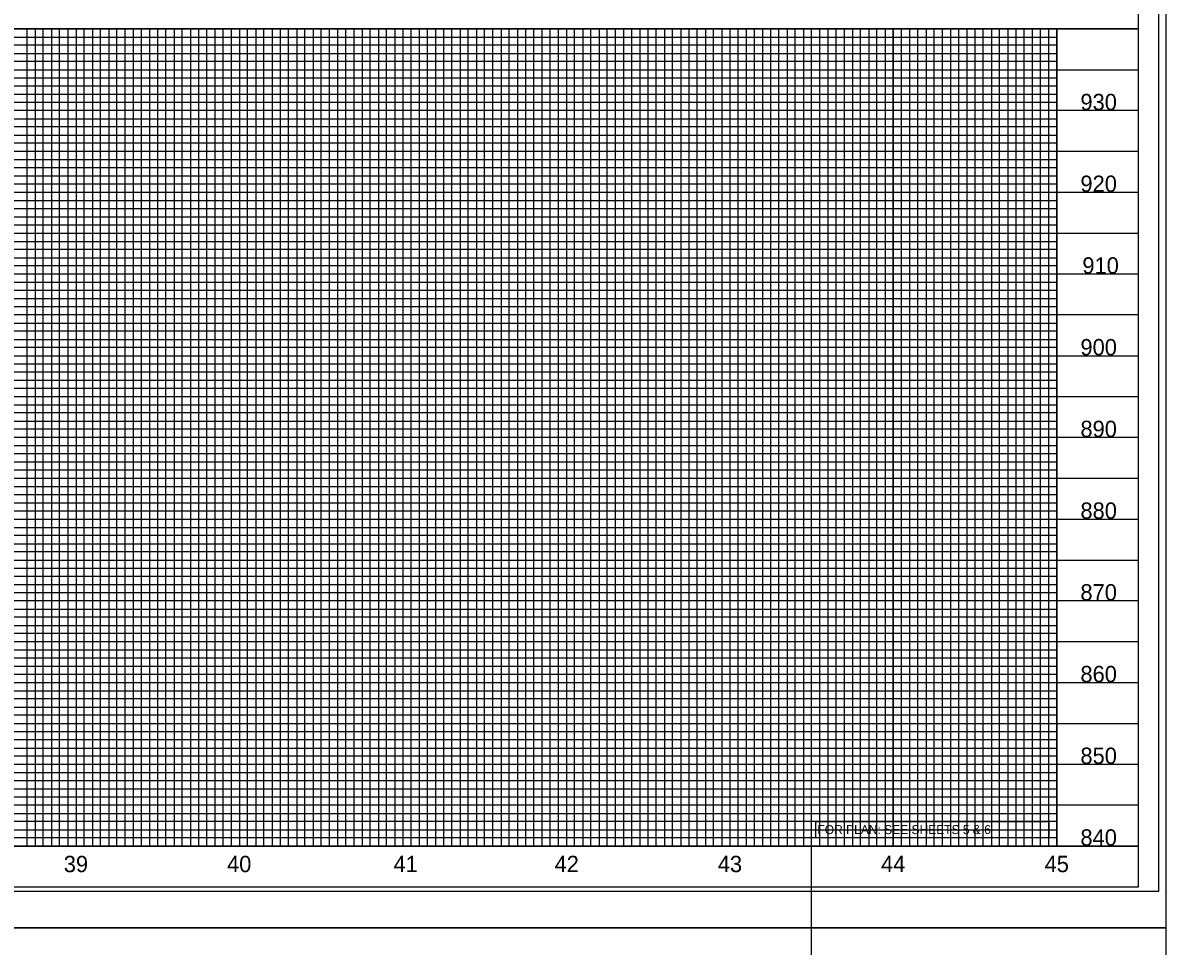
# Model space of a CAD drawing. Extents: x 1967929 to 1975641, y 546296 to 568534.
# Drawn here: x 1970849 to 1971549, y 567423 to 567988 of the extents above; entities that cross this region are included whole.
import ezdxf

# ---------------------------------------------------------------- set-up
doc = ezdxf.new("R2010")
doc.units = 0
for name, color, linetype in [('Exist Vertical Profile Horizontal Axis Label Major', 7, 'Continuous'), ('Exist Vertical Profile Vertical Axis Label', 7, 'Continuous'), ('Old_Level_60', 7, 'Continuous'), ('Prop Grid Mask', 7, 'Continuous'), ('Scratch_Level_3', 7, 'Continuous'), ('Sheet Cutting Line CELL', 7, 'Continuous'), ('Sheet Plot Border Inside CELL', 7, 'Continuous'), ('Sheet Plot Border Outside CELL', 7, 'Continuous'), ('Sheet Profile CELL', 7, 'Continuous'), ('Sheet Profile Grid Major CELL', 7, 'Continuous'), ('Sheet Profile Grid Middle CELL', 7, 'Continuous'), ('Sheet Profile Grid Minor CELL', 7, 'Continuous')]:
    doc.layers.add(name, color=color, linetype=linetype)

msp = doc.modelspace()

# ---------------------------------------------------------------- linework, layer by layer
at = {"layer": 'Old_Level_60'}
msp.add_line((1971548.95, 567456.36), (1971548.95, 567456.36), dxfattribs=at)
at = {"layer": 'Prop Grid Mask'}
msp.add_lwpolyline([(1971334.04, 567498.93), (1971476.5, 567498.93), (1971476.5, 567488.91), (1971334.04, 567488.91)], close=True, dxfattribs=at)
at = {"layer": 'Scratch_Level_3'}
for points in [[(1970081.45, 567983.86), (1970081.45, 567483.86), (1971481.45, 567483.86), (1971481.45, 567983.86)], [(1970081.45, 567983.86), (1970081.45, 567483.86), (1971381.45, 567483.86), (1971381.45, 567983.86)], [(1970081.45, 567983.86), (1970081.45, 567483.86), (1971481.45, 567483.86), (1971481.45, 567983.86)], [(1970081.45, 567983.86), (1970081.45, 567483.86), (1971481.45, 567483.86), (1971481.45, 567752.23), (1971481.45, 567983.86), (1971331.4, 567983.86)], [(1970081.45, 567508.86), (1970081.45, 567008.86), (1971481.45, 567008.86), (1971481.5, 567312.53), (1971331.45, 567312.51), (1971331.4, 567508.86)]]:
    msp.add_lwpolyline(points, close=True, dxfattribs=at)
at = {"layer": 'Sheet Cutting Line CELL'}
msp.add_line((1969864.45, 567433.86), (1971548.45, 567433.86), dxfattribs=at)
at = {"layer": 'Sheet Plot Border Inside CELL'}
msp.add_lwpolyline([(1969877.45, 567456.31), (1971543.95, 567456.31), (1971543.95, 568511.41), (1969877.45, 568511.41)], close=True, dxfattribs=at)
at = {"layer": 'Sheet Plot Border Outside CELL'}
for points in [[(1969864.45, 567433.86), (1971548.45, 567433.86), (1971548.45, 568533.86), (1969864.45, 568533.86)], [(1969864.45, 566333.86), (1971548.45, 566333.86), (1971548.45, 567433.86), (1969864.45, 567433.86)]]:
    msp.add_lwpolyline(points, close=True, dxfattribs=at)
at = {"layer": 'Sheet Profile CELL'}
for p, q in [((1971531.45, 567983.86), (1970031.45, 567983.86)), ((1971531.45, 567483.86), (1970031.45, 567483.86))]:
    msp.add_line(p, q, dxfattribs=at)
msp.add_lwpolyline([(1971531.45, 568508.86), (1970031.45, 568508.86), (1970031.45, 567458.86), (1971531.45, 567458.86)], close=True, dxfattribs=at)
at = {"layer": 'Sheet Profile Grid Major CELL'}
for points in [[(1971531.45, 567933.86), (1970031.45, 567933.86), (1970031.45, 567983.86), (1971531.45, 567983.86)], [(1970881.45, 567983.86), (1970881.45, 567483.86), (1970931.45, 567483.86), (1970931.45, 567983.86)], [(1970981.45, 567983.86), (1970981.45, 567483.86), (1971031.45, 567483.86), (1971031.45, 567983.86)], [(1971081.45, 567983.86), (1971081.45, 567483.86), (1971131.45, 567483.86), (1971131.45, 567983.86)], [(1971181.45, 567983.86), (1971181.45, 567483.86), (1971231.45, 567483.86), (1971231.45, 567983.86)], [(1971281.45, 567983.86), (1971281.45, 567483.86), (1971331.45, 567483.86), (1971331.45, 567983.86)], [(1971381.45, 567983.86), (1971381.45, 567483.86), (1971431.45, 567483.86), (1971431.45, 567983.86)], [(1971481.45, 567983.86), (1971481.45, 567483.86), (1971531.45, 567483.86)], [(1971531.45, 567833.86), (1970031.45, 567833.86), (1970031.45, 567883.86), (1971531.45, 567883.86)], [(1971531.45, 567733.86), (1970031.45, 567733.86), (1970031.45, 567783.86), (1971531.45, 567783.86)], [(1971531.45, 567633.86), (1970031.45, 567633.86), (1970031.45, 567683.86), (1971531.45, 567683.86)], [(1971531.45, 567533.86), (1970031.45, 567533.86), (1970031.45, 567583.86), (1971531.45, 567583.86)]]:
    msp.add_lwpolyline(points, dxfattribs=at)
at = {"layer": 'Sheet Profile Grid Middle CELL'}
for points in [[(1970031.45, 567983.86), (1970031.45, 567958.86), (1971531.45, 567958.86)], [(1970856.45, 567983.86), (1970856.45, 567483.86), (1970906.45, 567483.86), (1970906.45, 567983.86)], [(1970956.45, 567983.86), (1970956.45, 567483.86), (1971006.45, 567483.86), (1971006.45, 567983.86)], [(1971056.45, 567983.86), (1971056.45, 567483.86), (1971106.45, 567483.86), (1971106.45, 567983.86)], [(1971156.45, 567983.86), (1971156.45, 567483.86), (1971206.45, 567483.86), (1971206.45, 567983.86)], [(1971256.45, 567983.86), (1971256.45, 567483.86), (1971306.45, 567483.86), (1971306.45, 567983.86)], [(1971356.45, 567983.86), (1971356.45, 567483.86), (1971406.45, 567483.86), (1971406.45, 567983.86)], [(1971456.45, 567983.86), (1971456.45, 567483.86)], [(1971531.45, 567908.86), (1970031.45, 567908.86), (1970031.45, 567858.86), (1971531.45, 567858.86)], [(1971531.45, 567808.86), (1970031.45, 567808.86), (1970031.45, 567758.86), (1971531.45, 567758.86)], [(1971531.45, 567708.86), (1970031.45, 567708.86), (1970031.45, 567658.86), (1971531.45, 567658.86)], [(1971531.45, 567608.86), (1970031.45, 567608.86), (1970031.45, 567558.86), (1971531.45, 567558.86)], [(1971531.45, 567508.86), (1970031.45, 567508.86)]]:
    msp.add_lwpolyline(points, dxfattribs=at)
at = {"layer": 'Sheet Profile Grid Minor CELL'}
for points in [[(1970851.45, 567983.86), (1970851.45, 567483.86), (1970861.45, 567483.86), (1970861.45, 567983.86)], [(1970866.45, 567983.86), (1970866.45, 567483.86), (1970871.45, 567483.86), (1970871.45, 567983.86)], [(1970876.45, 567983.86), (1970876.45, 567483.86), (1970886.45, 567483.86), (1970886.45, 567983.86)], [(1970891.45, 567983.86), (1970891.45, 567483.86), (1970896.45, 567483.86), (1970896.45, 567983.86)], [(1970901.45, 567983.86), (1970901.45, 567483.86), (1970911.45, 567483.86), (1970911.45, 567983.86)], [(1970916.45, 567983.86), (1970916.45, 567483.86), (1970921.45, 567483.86), (1970921.45, 567983.86)], [(1970926.45, 567983.86), (1970926.45, 567483.86), (1970936.45, 567483.86), (1970936.45, 567983.86)], [(1970941.45, 567983.86), (1970941.45, 567483.86), (1970946.45, 567483.86), (1970946.45, 567983.86)], [(1970951.45, 567983.86), (1970951.45, 567483.86), (1970961.45, 567483.86), (1970961.45, 567983.86)], [(1970966.45, 567983.86), (1970966.45, 567483.86), (1970971.45, 567483.86), (1970971.45, 567983.86)], [(1970976.45, 567983.86), (1970976.45, 567483.86), (1970986.45, 567483.86), (1970986.45, 567983.86)], [(1970991.45, 567983.86), (1970991.45, 567483.86), (1970996.45, 567483.86), (1970996.45, 567983.86)], [(1971001.45, 567983.86), (1971001.45, 567483.86), (1971011.45, 567483.86), (1971011.45, 567983.86)], [(1971016.45, 567983.86), (1971016.45, 567483.86), (1971021.45, 567483.86), (1971021.45, 567983.86)], [(1971026.45, 567983.86), (1971026.45, 567483.86), (1971036.45, 567483.86), (1971036.45, 567983.86)], [(1971041.45, 567983.86), (1971041.45, 567483.86), (1971046.45, 567483.86), (1971046.45, 567983.86)], [(1971051.45, 567983.86), (1971051.45, 567483.86), (1971061.45, 567483.86), (1971061.45, 567983.86)], [(1971066.45, 567983.86), (1971066.45, 567483.86), (1971071.45, 567483.86), (1971071.45, 567983.86)], [(1971076.45, 567983.86), (1971076.45, 567483.86), (1971086.45, 567483.86), (1971086.45, 567983.86)], [(1971091.45, 567983.86), (1971091.45, 567483.86), (1971096.45, 567483.86), (1971096.45, 567983.86)], [(1971101.45, 567983.86), (1971101.45, 567483.86)], [(1971101.45, 567483.86), (1971111.45, 567483.86), (1971111.45, 567983.86)], [(1971116.45, 567983.86), (1971116.45, 567483.86), (1971121.45, 567483.86), (1971121.45, 567983.86)], [(1971126.45, 567983.86), (1971126.45, 567483.86), (1971136.45, 567483.86), (1971136.45, 567983.86)], [(1971141.45, 567983.86), (1971141.45, 567483.86), (1971146.45, 567483.86), (1971146.45, 567983.86)], [(1971151.45, 567983.86), (1971151.45, 567483.86), (1971161.45, 567483.86), (1971161.45, 567983.86)], [(1971166.45, 567983.86), (1971166.45, 567483.86), (1971171.45, 567483.86), (1971171.45, 567983.86)], [(1971176.45, 567983.86), (1971176.45, 567483.86), (1971186.45, 567483.86), (1971186.45, 567983.86)], [(1971191.45, 567983.86), (1971191.45, 567483.86), (1971196.45, 567483.86), (1971196.45, 567983.86)], [(1971201.45, 567983.86), (1971201.45, 567483.86), (1971211.45, 567483.86), (1971211.45, 567983.86)], [(1971216.45, 567983.86), (1971216.45, 567483.86), (1971221.45, 567483.86), (1971221.45, 567983.86)], [(1971226.45, 567983.86), (1971226.45, 567483.86), (1971236.45, 567483.86), (1971236.45, 567983.86)], [(1971241.45, 567983.86), (1971241.45, 567483.86), (1971246.45, 567483.86), (1971246.45, 567983.86)], [(1971251.45, 567983.86), (1971251.45, 567483.86), (1971261.45, 567483.86), (1971261.45, 567983.86)], [(1971266.45, 567983.86), (1971266.45, 567483.86), (1971271.45, 567483.86), (1971271.45, 567983.86)], [(1971276.45, 567983.86), (1971276.45, 567483.86), (1971286.45, 567483.86), (1971286.45, 567983.86)], [(1971291.45, 567983.86), (1971291.45, 567483.86), (1971296.45, 567483.86), (1971296.45, 567983.86)], [(1971301.45, 567983.86), (1971301.45, 567483.86), (1971311.45, 567483.86), (1971311.45, 567983.86)], [(1971316.45, 567983.86), (1971316.45, 567483.86), (1971321.45, 567483.86), (1971321.45, 567983.86)], [(1971326.45, 567983.86), (1971326.45, 567483.86), (1971336.45, 567483.86), (1971336.45, 567983.86)], [(1971341.45, 567983.86), (1971341.45, 567483.86), (1971346.45, 567483.86), (1971346.45, 567983.86)], [(1971351.45, 567983.86), (1971351.45, 567483.86), (1971361.45, 567483.86), (1971361.45, 567983.86)], [(1971366.45, 567983.86), (1971366.45, 567483.86), (1971371.45, 567483.86), (1971371.45, 567983.86)], [(1971376.45, 567983.86), (1971376.45, 567483.86), (1971386.45, 567483.86), (1971386.45, 567983.86)], [(1971391.45, 567983.86), (1971391.45, 567483.86), (1971396.45, 567483.86), (1971396.45, 567983.86)], [(1971401.45, 567983.86), (1971401.45, 567483.86), (1971411.45, 567483.86), (1971411.45, 567983.86)], [(1971416.45, 567983.86), (1971416.45, 567483.86)], [(1971416.45, 567483.86), (1971421.45, 567483.86), (1971421.45, 567983.86)], [(1971426.45, 567983.86), (1971426.45, 567483.86), (1971436.45, 567483.86), (1971436.45, 567983.86)], [(1971441.45, 567983.86), (1971441.45, 567483.86), (1971446.45, 567483.86), (1971446.45, 567983.86)], [(1971451.45, 567983.86), (1971451.45, 567483.86), (1971461.45, 567483.86), (1971461.45, 567983.86)], [(1971466.45, 567983.86), (1971466.45, 567483.86), (1971471.45, 567483.86), (1971471.45, 567983.86)], [(1971476.45, 567983.86), (1971476.45, 567483.86), (1971486.45, 567483.86)], [(1970081.45, 567978.86), (1971481.45, 567978.86)], [(1971481.45, 567973.86), (1970081.45, 567973.86), (1970081.45, 567968.86), (1971481.45, 567968.86)], [(1971481.45, 567963.86), (1970081.45, 567963.86), (1970081.45, 567953.86), (1971481.45, 567953.86)], [(1971481.45, 567948.86), (1970081.45, 567948.86), (1970081.45, 567943.86), (1971481.45, 567943.86)], [(1971481.45, 567938.86), (1970081.45, 567938.86), (1970081.45, 567928.86), (1971481.45, 567928.86)], [(1971481.45, 567923.86), (1970081.45, 567923.86), (1970081.45, 567918.86), (1971481.45, 567918.86)], [(1971481.45, 567913.86), (1970081.45, 567913.86), (1970081.45, 567903.86), (1971481.45, 567903.86)], [(1971481.45, 567898.86), (1970081.45, 567898.86), (1970081.45, 567893.86), (1971481.45, 567893.86)], [(1971481.45, 567888.86), (1970081.45, 567888.86), (1970081.45, 567878.86), (1971481.45, 567878.86)], [(1971481.45, 567873.86), (1970081.45, 567873.86), (1970081.45, 567868.86), (1971481.45, 567868.86)], [(1971481.45, 567863.86), (1970081.45, 567863.86), (1970081.45, 567853.86), (1971481.45, 567853.86)], [(1971481.45, 567848.86), (1970081.45, 567848.86), (1970081.45, 567843.86), (1971481.45, 567843.86)], [(1971481.45, 567838.86), (1970081.45, 567838.86), (1970081.45, 567828.86), (1971481.45, 567828.86)], [(1971481.45, 567823.86), (1970081.45, 567823.86), (1970081.45, 567818.86), (1971481.45, 567818.86)], [(1971481.45, 567813.86), (1970081.45, 567813.86), (1970081.45, 567803.86), (1971481.45, 567803.86)], [(1971481.45, 567798.86), (1970081.45, 567798.86), (1970081.45, 567793.86), (1971481.45, 567793.86)], [(1971481.45, 567788.86), (1970081.45, 567788.86), (1970081.45, 567778.86), (1971481.45, 567778.86)], [(1971481.45, 567773.86), (1970081.45, 567773.86), (1970081.45, 567768.86), (1971481.45, 567768.86)], [(1971481.45, 567763.86), (1970081.45, 567763.86), (1970081.45, 567753.86), (1971481.45, 567753.86)], [(1971481.45, 567748.86), (1970081.45, 567748.86), (1970081.45, 567743.86), (1971481.45, 567743.86)], [(1971481.45, 567738.86), (1970081.45, 567738.86), (1970081.45, 567728.86), (1971481.45, 567728.86)], [(1971481.45, 567723.86), (1970081.45, 567723.86), (1970081.45, 567718.86), (1971481.45, 567718.86)], [(1971481.45, 567713.86), (1970081.45, 567713.86), (1970081.45, 567703.86), (1971481.45, 567703.86)], [(1971481.45, 567698.86), (1970081.45, 567698.86), (1970081.45, 567693.86), (1971481.45, 567693.86)], [(1971481.45, 567688.86), (1970081.45, 567688.86)], [(1970081.45, 567678.86), (1971481.45, 567678.86)], [(1971481.45, 567673.86), (1970081.45, 567673.86), (1970081.45, 567668.86), (1971481.45, 567668.86)], [(1971481.45, 567663.86), (1970081.45, 567663.86)], [(1970081.45, 567653.86), (1971481.45, 567653.86)], [(1971481.45, 567648.86), (1970081.45, 567648.86), (1970081.45, 567643.86), (1971481.45, 567643.86)], [(1971481.45, 567638.86), (1970081.45, 567638.86), (1970081.45, 567628.86), (1971481.45, 567628.86)], [(1971481.45, 567623.86), (1970081.45, 567623.86), (1970081.45, 567618.86), (1971481.45, 567618.86)], [(1971481.45, 567613.86), (1970081.45, 567613.86), (1970081.45, 567603.86), (1971481.45, 567603.86)], [(1971481.45, 567598.86), (1970081.45, 567598.86), (1970081.45, 567593.86), (1971481.45, 567593.86)], [(1971481.45, 567588.86), (1970081.45, 567588.86), (1970081.45, 567578.86), (1971481.45, 567578.86)], [(1971481.45, 567573.86), (1970081.45, 567573.86), (1970081.45, 567568.86), (1971481.45, 567568.86)], [(1971481.45, 567563.86), (1970081.45, 567563.86), (1970081.45, 567553.86), (1971481.45, 567553.86)], [(1971481.45, 567548.86), (1970081.45, 567548.86), (1970081.45, 567543.86), (1971481.45, 567543.86)], [(1971481.45, 567538.86), (1970081.45, 567538.86), (1970081.45, 567528.86), (1971481.45, 567528.86)], [(1971481.45, 567523.86), (1970081.45, 567523.86), (1970081.45, 567518.86), (1971481.45, 567518.86)], [(1971481.45, 567513.86), (1970081.45, 567513.86), (1970081.45, 567503.86), (1971481.45, 567503.86)], [(1971481.45, 567498.86), (1970081.45, 567498.86), (1970081.45, 567493.86), (1971481.45, 567493.86)], [(1971481.45, 567488.86), (1970081.45, 567488.86), (1970081.45, 567483.86), (1971481.45, 567483.86)]]:
    msp.add_lwpolyline(points, dxfattribs=at)

# ---------------------------------------------------------------- texts
at = {"layer": 'Exist Vertical Profile Horizontal Axis Label Major'}
for s, p in [('39', (1970873.96, 567467.89)), ('40', (1970973.84, 567467.89)), ('41', (1971075.68, 567467.89)), ('42', (1971174.22, 567467.89)), ('43', (1971274.06, 567467.89)), ('44', (1971373.9, 567467.89)), ('45', (1971473.99, 567467.89))]:
    msp.add_text(s, height=10, dxfattribs=at).set_placement(p)
at = {"layer": 'Exist Vertical Profile Vertical Axis Label'}
for s, p in [('930', (1971495.92, 567934.11)), ('920', (1971495.92, 567884.11)), ('910', (1971497.11, 567834.11)), ('900', (1971495.92, 567784.11)), ('890', (1971495.92, 567734.11)), ('880', (1971495.92, 567684.11)), ('870', (1971495.92, 567634.11)), ('860', (1971495.92, 567584.11)), ('850', (1971495.92, 567534.11)), ('840', (1971495.92, 567484.11))]:
    msp.add_text(s, height=10, dxfattribs=at).set_placement(p)
at = {"layer": 'Prop Grid Mask'}
msp.add_text('FOR PLAN: SEE SHEETS 5 & 6', height=5.4932, dxfattribs=at).set_placement((1971335.03, 567491.19))

doc.saveas('drawing.dxf')
